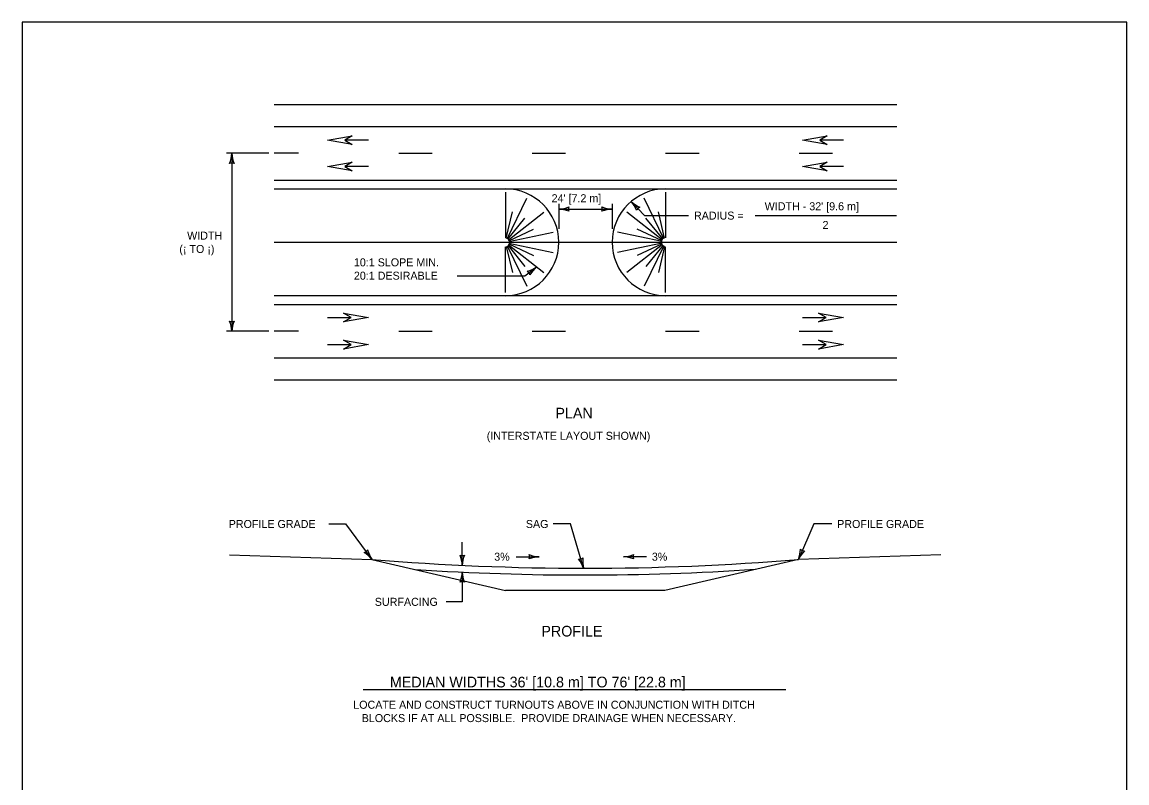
# Model space of a CAD drawing. Extents: x 49991.4 to 50021, y 49987.6 to 50011.4.
# Drawn here: x 50000.34 to 50008.61, y 50005.56 to 50011.26 of the extents above; entities that cross this region are included whole.
import ezdxf

# ---------------------------------------------------------------- set-up
doc = ezdxf.new("R2010")
doc.units = 0
for name, color, linetype in [('Level 1', 7, 'Continuous'), ('Level 2', 7, 'Continuous'), ('Level 3', 7, 'Continuous'), ('Level 4', 7, 'Continuous'), ('Level 5', 7, 'Continuous')]:
    doc.layers.add(name, color=color, linetype=linetype)

msp = doc.modelspace()

# ---------------------------------------------------------------- linework, layer by layer
at = {"layer": 'Level 1'}
for p, q in [((50002.2239, 50010.6464), (50006.8905, 50010.6464)), ((50002.2239, 50010.4797), (50006.8905, 50010.4797)), ((50002.9311, 50010.3785), (50002.7532, 50010.3785)), ((50006.4905, 50010.3785), (50006.3126, 50010.3785)), ((50002.4081, 50010.2797), (50002.2239, 50010.2797)), ((50003.1581, 50010.2797), (50003.4081, 50010.2797)), ((50004.1581, 50010.2797), (50004.4081, 50010.2797)), ((50005.1581, 50010.2797), (50005.4081, 50010.2797)), ((50006.1581, 50010.2797), (50006.4081, 50010.2797)), ((50002.9311, 50010.1813), (50002.7532, 50010.1813)), ((50006.4905, 50010.1813), (50006.3126, 50010.1813)), ((50002.2239, 50010.0797), (50006.8905, 50010.0797)), ((50002.2239, 50010.0131), (50006.8905, 50010.0131)), ((50003.9572, 50009.9892), (50003.9572, 50009.6461)), ((50005.1572, 50009.9892), (50005.1572, 50009.6461)), ((50003.9703, 50009.6399), (50004.1179, 50009.9426)), ((50005.1441, 50009.6399), (50004.9965, 50009.9426)), ((50003.9642, 50009.6435), (50004.0097, 50009.8406)), ((50003.979, 50009.6301), (50004.2461, 50009.8388)), ((50005.1354, 50009.6301), (50004.8683, 50009.8388)), ((50005.1502, 50009.6435), (50005.1047, 50009.8406)), ((50003.9755, 50009.6357), (50004.104, 50009.7944)), ((50005.1389, 50009.6357), (50005.0104, 50009.7944)), ((50003.9822, 50009.6247), (50004.1687, 50009.7117)), ((50003.9834, 50009.6186), (50004.3159, 50009.6893)), ((50005.131, 50009.6186), (50004.7985, 50009.6893)), ((50005.1322, 50009.6247), (50004.9457, 50009.7117)), ((50003.9572, 50009.237), (50003.9572, 50009.5801)), ((50003.9642, 50009.5826), (50004.0097, 50009.3856)), ((50003.9703, 50009.5862), (50004.1179, 50009.2835)), ((50003.9755, 50009.5904), (50004.104, 50009.4317)), ((50003.979, 50009.596), (50004.2461, 50009.3873)), ((50003.9822, 50009.6014), (50004.1687, 50009.5145)), ((50003.9834, 50009.6075), (50004.3159, 50009.5368)), ((50005.131, 50009.6075), (50004.7985, 50009.5368)), ((50005.1354, 50009.596), (50004.8683, 50009.3873)), ((50005.1322, 50009.6014), (50004.9457, 50009.5145)), ((50005.1441, 50009.5862), (50004.9965, 50009.2835)), ((50005.1389, 50009.5904), (50005.0104, 50009.4317)), ((50005.1502, 50009.5826), (50005.1047, 50009.3856)), ((50005.1572, 50009.237), (50005.1572, 50009.5801)), ((50006.8905, 50009.2131), (50002.2239, 50009.2131)), ((50002.2239, 50009.1464), (50006.8905, 50009.1464)), ((50002.6239, 50009.0504), (50002.8018, 50009.0504)), ((50006.1833, 50009.0504), (50006.3612, 50009.0504)), ((50002.4081, 50008.9464), (50002.2239, 50008.9464)), ((50003.1581, 50008.9464), (50003.4081, 50008.9464)), ((50004.1581, 50008.9464), (50004.4081, 50008.9464)), ((50005.1581, 50008.9464), (50005.4081, 50008.9464)), ((50006.1581, 50008.9464), (50006.4081, 50008.9464)), ((50002.6239, 50008.8464), (50002.8018, 50008.8464)), ((50006.1833, 50008.8464), (50006.3612, 50008.8464)), ((50002.2239, 50008.7464), (50006.8905, 50008.7464)), ((50006.8905, 50008.5797), (50002.2239, 50008.5797)), ((50001.8905, 50007.271), (50002.9572, 50007.2376)), ((50002.9572, 50007.2376), (50003.9572, 50007.0043)), ((50006.1531, 50007.2376), (50005.1531, 50007.0043)), ((50007.2197, 50007.271), (50006.1531, 50007.2376)), ((50005.1531, 50007.0043), (50003.9572, 50007.0043))]:
    msp.add_line(p, q, dxfattribs=at)
for points in [[(50008.6146, 50011.2628), (50000.3356, 50011.2628), (50000.3356, 50000.0624), (50008.6146, 50000.0624)], [(50002.8101, 50010.3457), (50002.6239, 50010.3785), (50002.8101, 50010.4115), (50002.7533, 50010.3785)], [(50006.3695, 50010.3457), (50006.1833, 50010.3785), (50006.3695, 50010.4115), (50006.3127, 50010.3785)], [(50002.8101, 50010.1485), (50002.6239, 50010.1813), (50002.8101, 50010.2143), (50002.7533, 50010.1813)], [(50006.3695, 50010.1485), (50006.1833, 50010.1813), (50006.3695, 50010.2143), (50006.3127, 50010.1813)], [(50002.7449, 50009.0832), (50002.9311, 50009.0504), (50002.7449, 50009.0174), (50002.8017, 50009.0504)], [(50006.3043, 50009.0832), (50006.4905, 50009.0504), (50006.3043, 50009.0174), (50006.3611, 50009.0504)], [(50002.7449, 50008.8792), (50002.9311, 50008.8464), (50002.7449, 50008.8134), (50002.8017, 50008.8464)], [(50006.3043, 50008.8792), (50006.4905, 50008.8464), (50006.3043, 50008.8134), (50006.3611, 50008.8464)]]:
    msp.add_lwpolyline(points, close=True, dxfattribs=at)
for centre, start, end in [((50003.9572, 50009.6131), 270, 90), ((50005.1572, 50009.6131), 90, 270)]:
    msp.add_arc(centre, 0.4, start, end, dxfattribs=at)
at = {"layer": 'Level 2'}
for p, q in [((50005.8298, 50009.8129), (50006.8883, 50009.8129)), ((50002.8906, 50006.2622), (50006.0597, 50006.2622))]:
    msp.add_line(p, q, dxfattribs=at)
at = {"layer": 'Level 3'}
for p, q in [((50002.1839, 50010.2797), (50001.8674, 50010.2797)), ((50001.9074, 50010.2797), (50001.9074, 50008.9464)), ((50004.3572, 50009.9018), (50004.3572, 50009.7131)), ((50004.7564, 50009.9018), (50004.7564, 50009.7131)), ((50004.9004, 50009.9197), (50005.0005, 50009.8131)), ((50004.3581, 50009.8618), (50004.7553, 50009.8618)), ((50005.0005, 50009.8131), (50005.3305, 50009.8131)), ((50004.1034, 50009.3628), (50004.192, 50009.4296)), ((50003.5962, 50009.3628), (50004.1034, 50009.3628)), ((50002.1839, 50008.9464), (50001.8674, 50008.9464)), ((50002.6342, 50007.5025), (50002.7597, 50007.5025)), ((50002.7597, 50007.5025), (50002.9572, 50007.2376)), ((50004.4445, 50007.5025), (50004.316, 50007.5025)), ((50004.5433, 50007.171), (50004.4445, 50007.5025)), ((50006.2678, 50007.5025), (50006.1531, 50007.2376)), ((50006.4034, 50007.5025), (50006.2678, 50007.5025)), ((50003.6339, 50007.1931), (50003.6339, 50007.3665)), ((50004.0373, 50007.2574), (50004.2107, 50007.2574)), ((50005.0147, 50007.2574), (50004.8413, 50007.2574)), ((50003.6339, 50007.1419), (50003.6339, 50006.9192)), ((50003.6339, 50006.9192), (50003.5126, 50006.9192))]:
    msp.add_line(p, q, dxfattribs=at)
for centre, radius, start, end in [((50001.6853, 50010.2889), 0.2223, 337.45601, 357.63952), ((50002.1401, 50010.2912), 0.233, 182.82731, 202.07716), ((50001.9074, 50010.1515), 0.0548, 72.13882, 107.86118), ((50004.7322, 50009.7743), 0.2223, 20.66508, 40.84859), ((50005.0621, 50010.0874), 0.233, 226.03638, 245.28623), ((50004.3457, 50010.0945), 0.233, 272.82731, 292.07716), ((50004.348, 50009.6397), 0.2223, 67.45601, 87.63952), ((50004.4854, 50009.8618), 0.0548, 162.13882, 197.86118), ((50004.7656, 50010.0839), 0.2223, 247.45601, 267.63952), ((50004.6282, 50009.8618), 0.0548, 342.13882, 17.86118), ((50004.7679, 50009.6291), 0.233, 92.82731, 112.07716), ((50004.9882, 50009.8263), 0.0548, 115.34789, 151.07025), ((50004.0655, 50009.6124), 0.2223, 284.4864, 304.66991), ((50004.0896, 50009.3524), 0.0548, 19.16921, 54.89157), ((50004.3413, 50009.2507), 0.233, 129.8577, 149.10755), ((50001.9074, 50009.0746), 0.0548, 252.13882, 287.86118), ((50001.6747, 50008.9349), 0.233, 2.82731, 22.07716), ((50002.1295, 50008.9372), 0.2223, 157.45601, 177.63952), ((50005.935, 50007.3195), 0.233, 339.41501, 358.66486), ((50006.204, 50007.3553), 0.0548, 228.72652, 264.44888), ((50002.8806, 50007.3404), 0.0548, 288.8518, 324.57416), ((50002.7775, 50007.0893), 0.233, 39.54029, 58.79014), ((50003.1407, 50007.3631), 0.2223, 194.16899, 214.3525), ((50003.6339, 50007.3213), 0.0548, 252.13882, 287.86118), ((50003.4012, 50007.1816), 0.233, 2.82731, 22.07716), ((50003.856, 50007.1839), 0.2223, 157.45601, 177.63952), ((50004.2199, 50007.4795), 0.2223, 247.45601, 267.63952), ((50004.0826, 50007.2574), 0.0548, 342.13882, 17.86118), ((50004.2223, 50007.0247), 0.233, 92.82731, 112.07716), ((50004.5067, 50007.2939), 0.0548, 268.72422, 304.44658), ((50004.3235, 50007.0935), 0.233, 19.41271, 38.66256), ((50004.7588, 50007.2256), 0.2223, 174.04141, 194.22492), ((50004.8321, 50007.4795), 0.2223, 272.36048, 292.54399), ((50004.8298, 50007.0247), 0.233, 67.92284, 87.17269), ((50004.9695, 50007.2574), 0.0548, 162.13882, 197.86118), ((50006.3533, 50007.1409), 0.2223, 134.04371, 154.22722), ((50003.4118, 50007.1511), 0.2223, 337.45601, 357.63952), ((50003.6339, 50007.0137), 0.0548, 72.13882, 107.86118), ((50003.8666, 50007.1534), 0.233, 182.82731, 202.07716)]:
    msp.add_arc(centre, radius, start, end, dxfattribs=at)
at = {"layer": 'Level 4'}
for centre, start, end in [((50004.5551, 50026.3547), 265.22195, 274.77805), ((50004.5441, 50026.3041), 266.23693, 273.84172)]:
    msp.add_arc(centre, 19.1838, start, end, dxfattribs=at)
at = {"layer": 'Level 5'}
msp.add_line((50002.2239, 50009.6131), (50006.8905, 50009.6131), dxfattribs=at)

# ---------------------------------------------------------------- texts
at = {"layer": 'Level 2'}
for s, height, p in [("24' [7.2 m]", 0.06, (50004.3035, 50009.9131)), ("WIDTH - 32' [9.6 m]", 0.06, (50005.9002, 50009.8529)), ('RADIUS =', 0.06, (50005.3705, 50009.7831)), ('2', 0.06, (50006.3339, 50009.7129)), ('WIDTH', 0.06, (50001.5724, 50009.6331)), ('(¡ TO ¡)', 0.06, (50001.5142, 50009.5331)), ('10:1 SLOPE MIN.', 0.06, (50002.8219, 50009.4328)), ('20:1 DESIRABLE', 0.06, (50002.8219, 50009.3328)), ('PLAN', 0.08, (50004.3325, 50008.2931)), ('(INTERSTATE LAYOUT SHOWN)', 0.06, (50003.8175, 50008.1331)), ('PROFILE GRADE', 0.06, (50001.884, 50007.4725)), ('SAG', 0.06, (50004.1106, 50007.4725)), ('PROFILE GRADE', 0.06, (50006.4434, 50007.4725)), ('3%', 0.06, (50003.8734, 50007.2274)), ('3%', 0.06, (50005.0547, 50007.2274)), ('SURFACING', 0.06, (50002.9786, 50006.8892)), ('PROFILE', 0.08, (50004.227, 50006.6594)), ("MEDIAN WIDTHS 36' [10.8 m] TO 76' [22.8 m]", 0.08, (50003.0916, 50006.2782)), ('LOCATE AND CONSTRUCT TURNOUTS ABOVE IN CONJUNCTION WITH DITCH', 0.06, (50002.8171, 50006.1182)), ('BLOCKS IF AT ALL POSSIBLE.  PROVIDE DRAINAGE WHEN NECESSARY.', 0.06, (50002.8806, 50006.0182))]:
    msp.add_text(s, height=height, dxfattribs=at).set_placement(p)

doc.saveas('drawing.dxf')
